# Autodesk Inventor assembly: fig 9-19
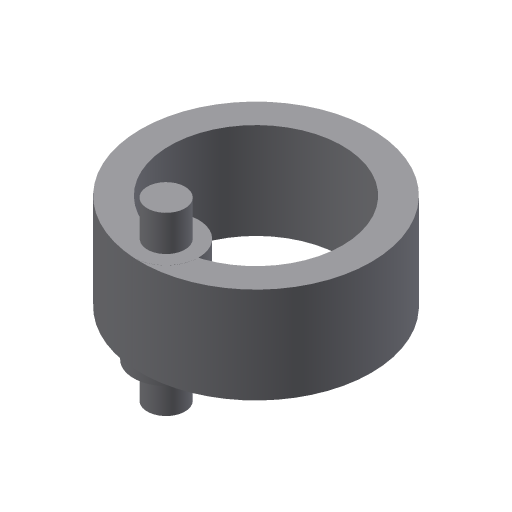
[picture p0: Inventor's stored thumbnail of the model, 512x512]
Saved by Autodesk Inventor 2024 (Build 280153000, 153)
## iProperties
Shininess: 64.0
Length Units: 11269
Angle Units: 11279
Time Units: 11290
Mass Units: 11283
Length Display Precision: 3
Angle Display Precision: 2
Created: 2002-01
Part Number: fig 9-19
Document SubType Name: Assembly
Designer: ***
Density: 0.0
Volumn: 0.0
Area: 0.0
PropertySet Name: Model Information
Control State: 0
Master: False
Checked Out: False
Author: ***
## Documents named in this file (3)
- D:\PROJECTS\Project 2023\RESOURCES INVENTOR 2024\RESOURCES INVENTOR 2024\Inventor_2023_Part\Inventor_2024_Part\c09_Inv_2024_prt\fig 9-19.iam
- D:\PROJECTS\Project 2023\RESOURCES INVENTOR 2024\RESOURCES INVENTOR 2024\Inventor_2023_Part\Inventor_2024_Part\c09_Inv_2024_prt\Part8.ipt
- D:\PROJECTS\Project 2023\RESOURCES INVENTOR 2024\RESOURCES INVENTOR 2024\Inventor_2023_Part\Inventor_2024_Part\c09_Inv_2024_prt\Part9.ipt
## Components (2 placed, 2 different names)
1. Part8:1 — Flush:1
2. Part9:1 — Flush:1
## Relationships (1: Flush 1)
- Flush:1: Part8:1 ↔ Part9:1
